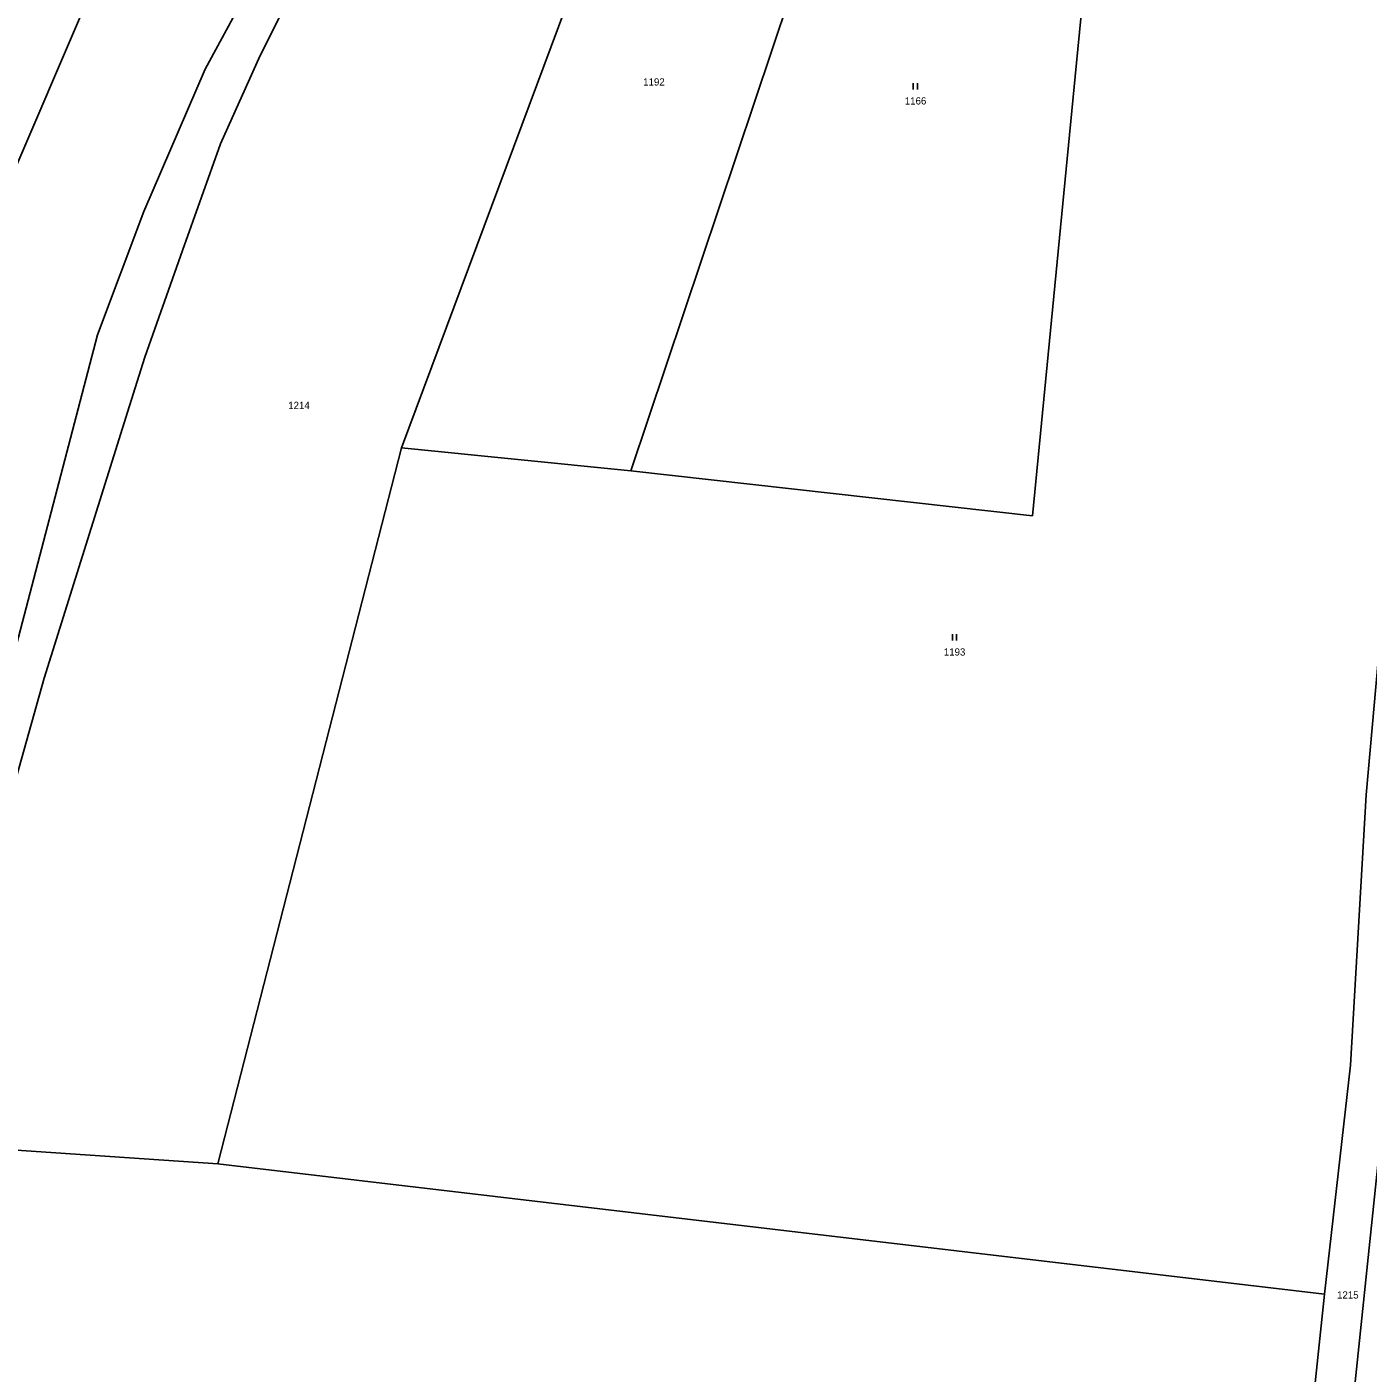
# Model space of a CAD drawing. Extents: x -746176 to -739709, y -1127410 to -1124482.
# Drawn here: x -742787.6 to -742472.1, y -1126433.2 to -1126116.6 of the extents above; entities that cross this region are included whole.
import ezdxf

# ---------------------------------------------------------------- set-up
doc = ezdxf.new("R2010")
doc.units = 0
for name, color, linetype in [('Hranice parcel', 7, 'Continuous'), ('Parcelní čísla', 7, 'Continuous'), ('Značky kultur', 7, 'Continuous')]:
    doc.layers.add(name, color=color, linetype=linetype)

msp = doc.modelspace()

# ---------------------------------------------------------------- linework, layer by layer
at = {"layer": 'Hranice parcel'}
for p, q in [((-742582.8, -1126033.87), (-742645.51, -1126221.02)), ((-742699.51, -1126215.67), (-742742.72, -1126384.02)), ((-742645.51, -1126221.02), (-742699.51, -1126215.67)), ((-742814.62, -1126379.12), (-742742.72, -1126384.02))]:
    msp.add_line(p, q, dxfattribs=at)
for points in [[(-742742.47, -1125964.26), (-742745.94, -1125988.79), (-742759.05, -1126076.89), (-742837.32, -1126259.46)], [(-742655.18, -1126009.8), (-742669.27, -1126025.18), (-742694.82, -1126057.02), (-742704.11, -1126071.12), (-742721.29, -1126100.47), (-742732.76, -1126123.33), (-742742.1, -1126144.14), (-742751, -1126169.24), (-742759.9, -1126194.33), (-742763.48, -1126205.79), (-742783.53, -1126269.84), (-742800.78, -1126331.04), (-742814.62, -1126379.12)], [(-742615.01, -1126025.64), (-742655.41, -1126097.45), (-742699.51, -1126215.67)], [(-742530.79, -1126023.12), (-742541.03, -1126128.32), (-742551.09, -1126231.6), (-742645.51, -1126221.02)], [(-742433.87, -1126052.94), (-742447.8, -1126100.68), (-742456.41, -1126109.29), (-742463.16, -1126192.21), (-742472.54, -1126297.27), (-742476.24, -1126360.79), (-742482.39, -1126414.71)], [(-742793.63, -1126275.74), (-742771.03, -1126189.05), (-742760.08, -1126160.03), (-742745.65, -1126126.59), (-742736.67, -1126109.84)], [(-742521.95, -1126773.52), (-742504.56, -1126672.68), (-742497, -1126628.23), (-742488.98, -1126567.9), (-742478.35, -1126466.13), (-742467.6, -1126363.23), (-742463.32, -1126296.13), (-742459.73, -1126263.65), (-742452.82, -1126263.88), (-742450.23, -1126260.63), (-742452.38, -1126257.65), (-742458.75, -1126256.81), (-742455.22, -1126201.03)], [(-742742.72, -1126384.02), (-742612.26, -1126399.4), (-742482.39, -1126414.71)], [(-742482.39, -1126414.71), (-742498.43, -1126567.43), (-742506.05, -1126624.82), (-742531.03, -1126759.57)]]:
    msp.add_lwpolyline(points, dxfattribs=at)
at = {"layer": 'Značky kultur'}
for p, q in [((-742579.101, -1126131.34), (-742579.101, -1126129.84)), ((-742578.1, -1126131.34), (-742578.1, -1126129.84)), ((-742569.921, -1126260.94), (-742569.921, -1126259.44)), ((-742568.92, -1126260.94), (-742568.92, -1126259.44))]:
    msp.add_line(p, q, dxfattribs=at)

# ---------------------------------------------------------------- texts
at = {"layer": 'Parcelní čísla'}
for s, p in [('1192', (-742642.637, -1126130.43)), ('1166', (-742581.097, -1126134.89)), ('1214', (-742726.137, -1126206.51)), ('1193', (-742571.917, -1126264.49)), ('1215', (-742479.417, -1126415.71))]:
    msp.add_text(s, height=1.7, dxfattribs=at).set_placement(p)

doc.saveas('drawing.dxf')
